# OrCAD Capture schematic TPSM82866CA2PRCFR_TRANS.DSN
size D; title: TPSM82866CA2: 6A, Step-Down Power Modules With Integrated / Inductor - MagPack™ Package; rev: 1.0; note: Datasheet: slusfl6c    EVM: sluud38a; note: Synchronous Step Down Converter
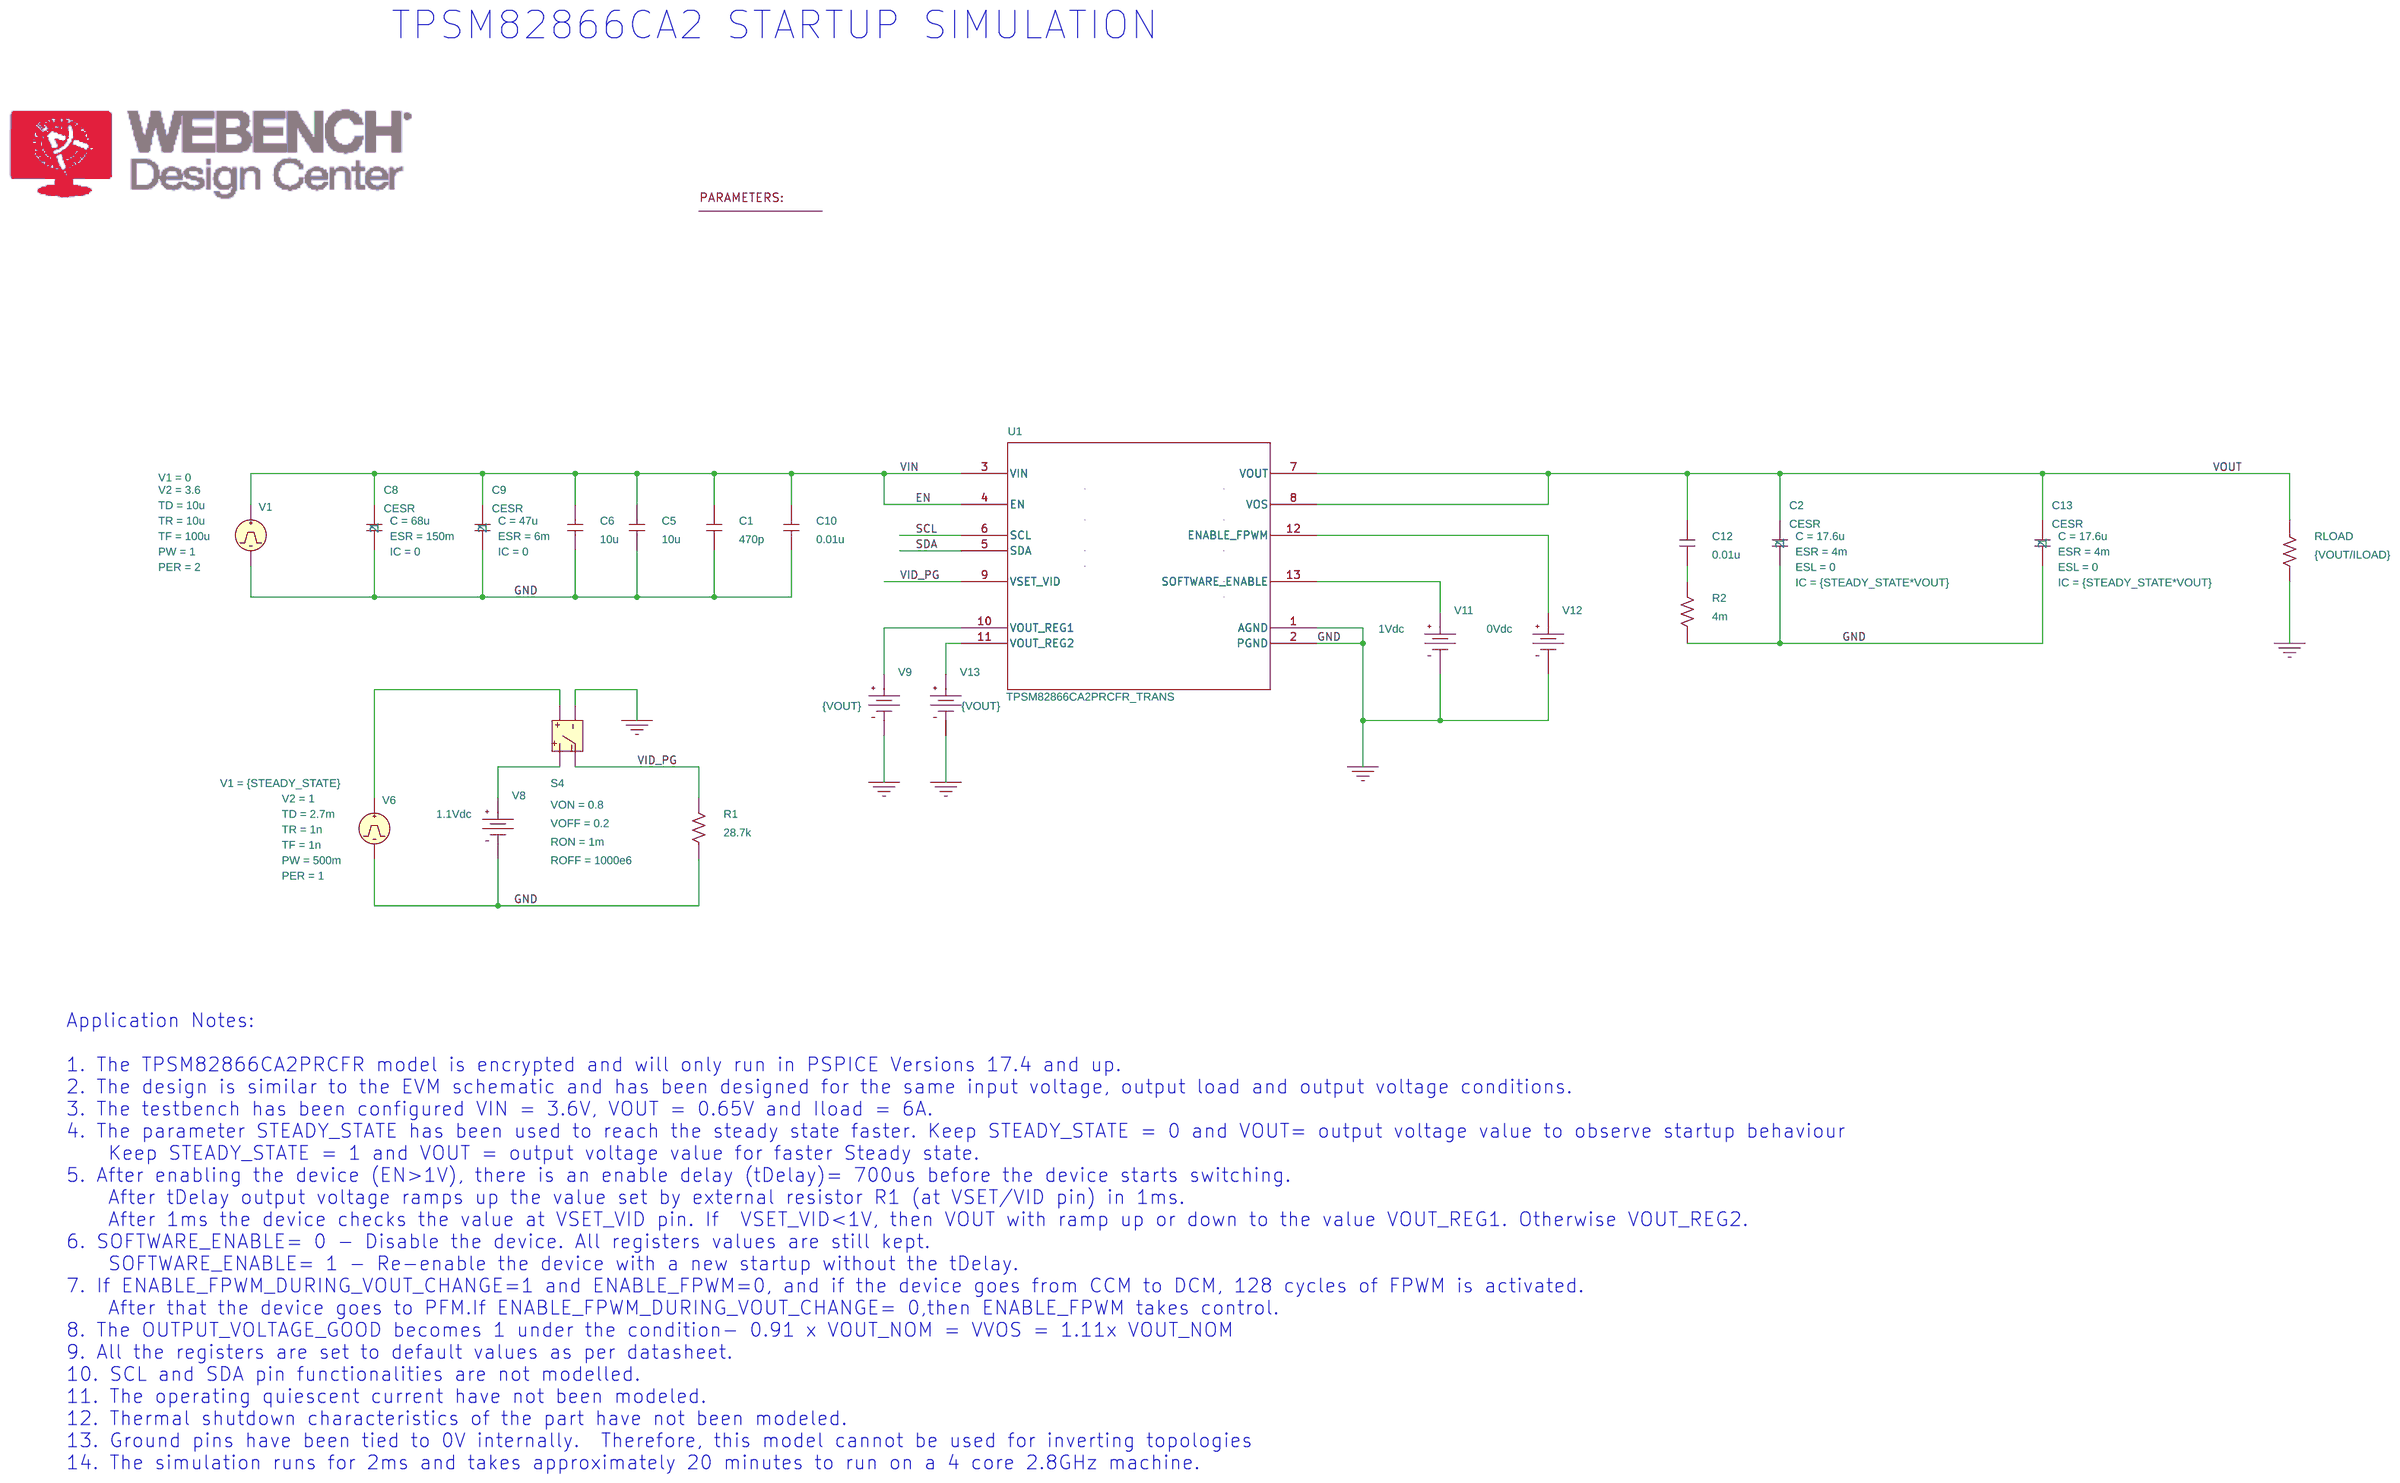
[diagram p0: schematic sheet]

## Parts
6  PARAM
C1  470p  [RAD/CK05]
C2  CESR
C5  10u  [RAD/CK05]
C6  10u  [RAD/CK05]
C8  CESR
C9  CESR
C10  0.01u  [RAD/CK05]
C12  0.01u  [RAD/CK05]
C13  CESR
R1  28.7k  [AX/RC05]
R2  4m  [AXRC05]
RLOAD  {VOUT/ILOAD}  [AX/RC05]
S4  S
U1  TPSM82866CA2PRCFR_TRANS  [RQY0009A-MFG]
V1  VPULSE
V6  VPULSE
V8  VDC
V9  VDC
V11  VDC
V12  VDC
V13  VDC

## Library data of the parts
6 = PARAM: ENABLE_FPWM_DURING_VOUT_CHANGE: 1; ENABLE_HICCUP: 1; ENABLE_OUTPUT_DISCHARGE: 1; STEADY_STATE: 0; VOUT: 0.65; VOUT_RAMP_SPEED: 3
C1 C5 C6 C10 C12 = C
C2 = CESR_2: C: 17.6u; ESL: 0; ESR: 4m; IC: {STEADY_STATE*VOUT}; PSpiceTemplate: X^@REFDES %1 %2 @MODEL PARAMS: ?C|C=@C||C=10U| ?ESR|ESR=@ESR||ESR=2M| ?ESL|ESL=@ESL||ESL=1N| ?IC|IC=@IC||IC=0|
C8 = CESR_1: C: 68u; ESR: 150m; IC: 0; PSpiceTemplate: X^@REFDES %1 %2 @MODEL PARAMS: ?C|C=@C||C=10U| ?ESR|ESR=@ESR||ESR=2M| ?ESL|ESL=@ESL||ESL=1N| ?IC|IC=@IC||IC=0|
C9 = CESR: C: 47u; ESR: 6m; IC: 0; PSpiceTemplate: X^@REFDES %1 %2 @MODEL PARAMS: ?C|C=@C||C=10U| ?ESR|ESR=@ESR||ESR=2M| ?ESL|ESL=@ESL||ESL=1N| ?IC|IC=@IC||IC=0|
C13 = CESR_3: C: 17.6u; ESL: 0; ESR: 4m; IC: {STEADY_STATE*VOUT}; PSpiceTemplate: X^@REFDES %1 %2 @MODEL PARAMS: ?C|C=@C||C=10U| ?ESR|ESR=@ESR||ESR=2M| ?ESL|ESL=@ESL||ESL=1N| ?IC|IC=@IC||IC=0|
R1 R2 RLOAD = R
S4 = S: ROFF: 1000e6; RON: 1m; VOFF: 0.2; VON: 0.8
U1 = TPSM82866CA2PRCFR_TRANS
V1 = VPULSE: PER: 2; PW: 1; TD: 10u; TF: 100u; TR: 10u; V1: 0; V2: 3.6
V6 = VPULSE: PER: 1; PW: 500m; TD: 2.7m; TF: 1n; TR: 1n; V1: {STEADY_STATE}; V2: 1
V8 = VDC: DC: 1.1Vdc
V9 V13 = VDC: DC: {VOUT}
V11 = VDC: DC: 1Vdc
V12 = VDC: DC: 0Vdc

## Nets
0: C1.1 C2.2 C5.1 C6.1 C8.2 C9.2 C10.1 C13.2 R1.1 R2.1 RLOAD.2 S4.1(2) U1.1(AGND) U1.2(PGND) V1.2(-) V6.2(-) V8.1(-) V9.1(-) V11.1(-) V12.1(-) V13.1(-)
EN: C1.2 C5.2 C6.2 C8.1 C9.1 C10.2 U1.3(VIN) U1.4(EN) V1.1(+)
SCL: U1.6(SCL)
SDA: U1.5(SDA)
VID_PG: R1.2 S4.3(4) U1.9(VSET_VID)
VOUT: C2.1 C12.2 C13.1 RLOAD.1 U1.7(VOUT) U1.8(VOS)
N16777552: U1.12(ENABLE_FPWM) V12.0(+)
N16777638: U1.13(SOFTWARE_ENABLE) V11.0(+)
N16777683: U1.10(VOUT_REG1) V9.0(+)
N16777693: U1.11(VOUT_REG2) V13.0(+)
N16777740: S4.0(1) V6.1(+)
N16777792: S4.2(3) V8.0(+)
N16780598: C12.1 R2.2

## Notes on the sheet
- TPSM82866CA2 STARTUP SIMULATION
- Application Notes:
  1. The TPSM82866CA2PRCFR model is encrypted and will only run in PSPICE Versions 17.4 and up.
  2. The design is similar to the EVM schematic and has been designed for the same input voltage, output load and output voltage conditions.
  3. The testbench has been configured VIN = 3.6V, VOUT = 0.65V and Iload = 6A.
  4. The parameter STEADY_STATE has been used to reach the steady state faster. Keep STEADY_STATE = 0 and VOUT= output voltage value to observe startup behaviour
      Keep STEADY_STATE = 1 and VOUT = output voltage value for faster Steady state.
  5. After enabling the device (EN>1V), there is an enable delay (tDelay)= 700us before the device starts switching.
      After tDelay output voltage ramps up the value set by external resistor R1 (at VSET/VID pin) in 1ms.
      After 1ms the device checks the value at VSET_VID pin. If  VSET_VID<1V, then VOUT with ramp up or down to the value VOUT_REG1. Otherwise VOUT_REG2.
  6. SOFTWARE_ENABLE= 0 - Disable the device. All registers values are still kept.
      SOFTWARE_ENABLE= 1 - Re-enable the device with a new startup without the tDelay.
  7. If ENABLE_FPWM_DURING_VOUT_CHANGE=1 and ENABLE_FPWM=0, and if the device goes from CCM to DCM, 128 cycles of FPWM is activated.
      After that the device goes to PFM.If ENABLE_FPWM_DURING_VOUT_CHANGE= 0,then ENABLE_FPWM takes control.
  8. The OUTPUT_VOLTAGE_GOOD becomes 1 under the condition- 0.91 x VOUT_NOM = VVOS = 1.11x VOUT_NOM
  9. All the registers are set to default values as per datasheet.
  10. SCL and SDA pin functionalities are not modelled.
  11. The operating quiescent current have not been modeled.
  12. Thermal shutdown characteristics of the part have not been modeled.
  13. Ground pins have been tied to 0V internally.  Therefore, this model cannot be used for inverting topologies
  14. The simulation runs for 2ms and takes approximately 20 minutes to run on a 4 core 2.8GHz machine.
